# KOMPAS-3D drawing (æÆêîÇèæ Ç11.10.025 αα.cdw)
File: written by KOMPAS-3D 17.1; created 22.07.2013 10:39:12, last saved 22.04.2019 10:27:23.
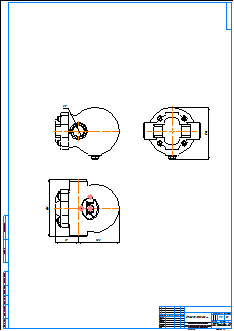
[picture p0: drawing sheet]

Sheet 1: A1, portrait

Title block, sheet 1: name: СТИМАКС А11.10.025 рр; material: Внимание! Данный продукт является объектом авторского права ООО «Торговый Дом АДЛ». / Запрещается изменение, копирование, распространение / (в том числе путем копирования на другие сайты и ресурсы в Интернете) / или любое иное использование информации и объектов без предварительного / согласия правообладателя (ООО «Торговый Дом АДЛ»).; mass: 9,9; sheets: 1; organisation: ООО "Торговый дом АДЛ"; sheet format: A1; stored path: \\adlc.lan\data\АДЛ_ПКД\3D-модели\ADL production\Конденсатоотводчики СТИМАКС\Поплавковые\Серия А11\KOMPAS 2D\СТИМАКС А11.10.025 рр.cdw

Views: Вид 1, Проекционный вид 2
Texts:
  Klimkovich
  ADL
Dimensions and other numbers on the sheet: 145; 59; 103; 1:1; 1; 9,9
